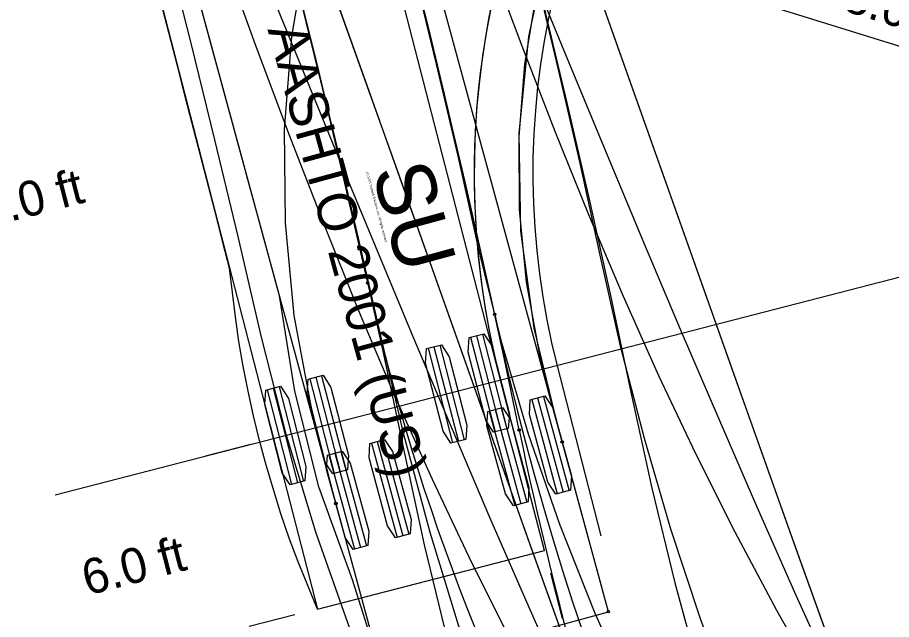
# Model space of a CAD drawing. Extents: x 916040 to 917457, y 328936 to 330267.
# Drawn here: x 916654.52 to 916684.33, y 329778.57 to 329799.1 of the extents above; entities that cross this region are included whole.
import ezdxf

# ---------------------------------------------------------------- set-up
doc = ezdxf.new("R2010")
doc.units = 0
for name, color, linetype in [('EB_LeftontoManchester_WB67', 7, 'Continuous'), ('EB_LeftontoManchester_WB67_v2', 7, 'Continuous'), ('NB_ThruontoManchester_WB67', 7, 'Continuous'), ('SU_IntoDriveway', 7, 'Continuous'), ('SU_IntoDriveway_Rt', 7, 'Continuous'), ('WB_RightontoManchester_WB67', 7, 'Continuous')]:
    doc.layers.add(name, color=color, linetype=linetype)

msp = doc.modelspace()

# ---------------------------------------------------------------- linework, layer by layer
at = {"layer": 'EB_LeftontoManchester_WB67'}
for points in [[(916682.241, 329777.749), (916681.118, 329780.876), (916680, 329784.008), (916678.884, 329787.143), (916677.771, 329790.282), (916676.657, 329793.423), (916675.541, 329796.565), (916674.423, 329799.708), (916673.299, 329802.851), (916672.17, 329805.993), (916671.034, 329809.133), (916669.889, 329812.272), (916668.734, 329815.408), (916667.569, 329818.541), (916666.392, 329821.67), (916665.202, 329824.794), (916663.999, 329827.914), (916662.781, 329831.029), (916661.548, 329834.138), (916660.298, 329837.24), (916659.033, 329840.337), (916657.749, 329843.426)], [(916678.932, 329775.573), (916677.819, 329778.595), (916676.808, 329781.65), (916675.901, 329784.736), (916675.099, 329787.849), (916674.397, 329790.994), (916673.698, 329794.181), (916672.962, 329797.377), (916672.193, 329800.579), (916671.392, 329803.785), (916670.559, 329806.993), (916669.696, 329810.202), (916668.803, 329813.41), (916667.88, 329816.616), (916666.928, 329819.819), (916665.947, 329823.018), (916664.938, 329826.212), (916663.901, 329829.401), (916662.836, 329832.582), (916661.742, 329835.757), (916660.621, 329838.924), (916659.472, 329842.082)], [(916669.601, 329778.228), (916668.593, 329781.538), (916667.695, 329784.881), (916666.908, 329788.244), (916666.151, 329791.57), (916665.373, 329794.873), (916664.574, 329798.156), (916663.752, 329801.421), (916662.906, 329804.669), (916662.034, 329807.902), (916661.138, 329811.12), (916660.215, 329814.324), (916659.267, 329817.515), (916658.293, 329820.694), (916657.292, 329823.861), (916656.265, 329827.016), (916655.212, 329830.159), (916654.132, 329833.291)], [(916673.116, 329778.01), (916671.993, 329781.154), (916670.875, 329784.298), (916669.76, 329787.441), (916668.646, 329790.581), (916667.532, 329793.719), (916666.416, 329796.854), (916665.297, 329799.984), (916664.174, 329803.111), (916663.044, 329806.232), (916661.907, 329809.349), (916660.762, 329812.46), (916659.607, 329815.564), (916658.441, 329818.663), (916657.264, 329821.754), (916656.074, 329824.839), (916654.871, 329827.916), (916653.654, 329830.986)]]:
    msp.add_lwpolyline(points, dxfattribs=at)
msp.add_circle((916670.794, 329788.972), 0.0417, dxfattribs=at)
msp.add_circle((916670.794, 329788.972), 0.0417, dxfattribs=at)
for centre, radius, start, end in [((916291.649, 329706.552), 388, 12.26429, 55.55708), ((916768.512, 329810.214), 100, 192.26429, 233.38938)]:
    msp.add_arc(centre, radius, start, end, dxfattribs=at)
at = {"layer": 'EB_LeftontoManchester_WB67_v2'}
for points in [[(916682.262, 329777.695), (916681.14, 329780.819), (916680.022, 329783.947), (916678.908, 329787.079), (916677.796, 329790.214), (916676.683, 329793.351), (916675.569, 329796.49), (916674.451, 329799.629), (916673.33, 329802.768), (916672.202, 329805.907), (916671.067, 329809.044), (916669.924, 329812.179), (916668.771, 329815.311), (916667.607, 329818.44), (916666.432, 329821.566), (916665.243, 329824.687), (916664.042, 329827.804), (916662.826, 329830.915), (916661.595, 329834.021), (916660.348, 329837.12), (916659.084, 329840.213), (916657.803, 329843.299)], [(916678.932, 329775.573), (916677.819, 329778.595), (916676.808, 329781.65), (916675.901, 329784.736), (916675.099, 329787.849), (916674.397, 329790.993), (916673.699, 329794.177), (916672.964, 329797.369), (916672.196, 329800.567), (916671.396, 329803.769), (916670.564, 329806.974), (916669.702, 329810.179), (916668.81, 329813.384), (916667.889, 329816.587), (916666.938, 329819.786), (916665.959, 329822.981), (916664.951, 329826.172), (916663.916, 329829.357), (916662.852, 329832.535), (916661.76, 329835.706), (916660.641, 329838.869), (916659.494, 329842.024)], [(916669.601, 329778.228), (916668.593, 329781.538), (916667.695, 329784.881), (916666.908, 329788.244), (916666.152, 329791.565), (916665.375, 329794.865), (916664.577, 329798.144), (916663.756, 329801.406), (916662.911, 329804.65), (916662.04, 329807.879), (916661.145, 329811.094), (916660.224, 329814.294), (916659.277, 329817.482), (916658.304, 329820.657), (916657.305, 329823.82), (916656.28, 329826.972), (916655.228, 329830.112), (916654.15, 329833.241)], [(916673.137, 329777.952), (916672.016, 329781.093), (916670.899, 329784.233), (916669.785, 329787.372), (916668.672, 329790.509), (916667.559, 329793.644), (916666.445, 329796.775), (916665.327, 329799.902), (916664.205, 329803.025), (916663.077, 329806.143), (916661.942, 329809.256), (916660.798, 329812.364), (916659.645, 329815.465), (916658.481, 329818.56), (916657.305, 329821.649), (916656.117, 329824.73), (916654.916, 329827.804), (916653.7, 329830.87)]]:
    msp.add_lwpolyline(points, dxfattribs=at)
msp.add_circle((916670.794, 329788.972), 0.0417, dxfattribs=at)
msp.add_circle((916670.794, 329788.972), 0.0417, dxfattribs=at)
for centre, radius, start, end in [((916291.649, 329706.552), 388, 12.26429, 55.55708), ((916768.512, 329810.214), 100, 192.26429, 233.38938)]:
    msp.add_arc(centre, radius, start, end, dxfattribs=at)
at = {"layer": 'NB_ThruontoManchester_WB67'}
for points in [[(916658.563, 329844.52), (916659.735, 329841.36), (916660.881, 329838.191), (916661.999, 329835.012), (916663.089, 329831.823), (916664.152, 329828.625), (916665.188, 329825.419), (916666.196, 329822.203), (916667.177, 329818.979), (916668.129, 329815.746), (916669.054, 329812.506), (916669.951, 329809.257), (916670.82, 329806.001), (916671.661, 329802.738), (916672.474, 329799.467), (916673.258, 329796.19), (916674.015, 329792.906), (916674.743, 329789.616), (916675.443, 329786.319), (916676.154, 329783.049), (916676.943, 329779.815), (916677.81, 329776.614)], [(916656.424, 329841.868), (916657.582, 329838.712), (916658.717, 329835.55), (916659.831, 329832.383), (916660.928, 329829.215), (916662.011, 329826.048), (916663.084, 329822.884), (916664.15, 329819.726), (916665.214, 329816.576), (916666.28, 329813.435), (916667.353, 329810.298), (916668.431, 329807.188), (916669.516, 329804.119), (916670.609, 329801.098), (916671.718, 329798.131), (916672.846, 329795.221), (916673.997, 329792.375), (916675.176, 329789.597), (916676.385, 329786.893), (916677.646, 329784.229), (916678.988, 329781.557), (916680.41, 329778.888), (916681.91, 329776.227)], [(916653.456, 329835.216), (916654.549, 329832.101), (916655.615, 329828.976), (916656.654, 329825.843), (916657.666, 329822.7), (916658.651, 329819.549), (916659.609, 329816.39), (916660.54, 329813.223), (916661.443, 329810.047), (916662.319, 329806.865), (916663.168, 329803.674), (916663.989, 329800.477), (916664.783, 329797.272), (916665.549, 329794.061), (916666.287, 329790.844), (916666.998, 329787.62), (916667.681, 329784.39), (916668.391, 329781.119), (916669.189, 329777.848)], [(916653.964, 329823.309), (916655.032, 329820.161), (916656.096, 329817.008), (916657.162, 329813.853), (916658.233, 329810.697), (916659.315, 329807.533), (916660.407, 329804.385), (916661.51, 329801.263), (916662.629, 329798.171), (916663.771, 329795.116), (916664.939, 329792.1), (916666.14, 329789.131), (916667.379, 329786.212), (916668.658, 329783.351), (916670, 329780.514), (916671.433, 329777.661)]]:
    msp.add_lwpolyline(points, dxfattribs=at)
msp.add_circle((916671.63, 329785.027), 0.0417, dxfattribs=at)
msp.add_circle((916671.63, 329785.027), 0.0417, dxfattribs=at)
for centre, radius, start, end in [((916291.649, 329706.552), 388, 11.6689, 55.55708), ((916800.902, 329811.725), 132, 191.6689, 207.94419)]:
    msp.add_arc(centre, radius, start, end, dxfattribs=at)
at = {"layer": 'SU_IntoDriveway'}
for p, q in [((916672.494, 329780.925), (916665.004, 329809.975)), ((916657.257, 329807.977), (916664.747, 329778.927)), ((916698.419, 329793.805), (916662.129, 329805.103)), ((916655.805, 329782.818), (916741.033, 329804.791)), ((916669.974, 329788.192), (916670.807, 329784.965)), ((916670.176, 329788.244), (916671.008, 329785.017)), ((916670.378, 329788.297), (916671.21, 329785.069)), ((916668.724, 329787.87), (916669.556, 329784.642)), ((916668.925, 329787.922), (916669.758, 329784.694)), ((916668.522, 329787.818), (916669.354, 329784.59)), ((916664.487, 329786.778), (916665.319, 329783.55)), ((916664.689, 329786.83), (916665.521, 329783.602)), ((916664.891, 329786.882), (916665.723, 329783.654)), ((916663.035, 329786.403), (916663.867, 329783.176)), ((916663.236, 329786.455), (916664.069, 329783.228)), ((916663.438, 329786.507), (916664.27, 329783.28)), ((916662.474, 329784.538), (916660.925, 329784.138)), ((916664.747, 329778.927), (916672.494, 329780.925)), ((916672.693, 329780.15), (916673.093, 329778.601)), ((916663.972, 329778.728), (916662.423, 329778.328))]:
    msp.add_line(p, q, dxfattribs=at)
for points in [[(916674.43, 329781.424), (916672.936, 329787.218), (916672.747, 329788.006), (916672.584, 329788.786), (916672.445, 329789.57), (916672.33, 329790.359), (916672.238, 329791.15), (916672.171, 329791.943), (916672.127, 329792.739), (916672.108, 329793.535), (916672.112, 329794.331), (916672.141, 329795.127), (916672.194, 329795.922), (916672.27, 329796.714), (916672.371, 329797.504), (916672.495, 329798.291), (916672.644, 329799.073), (916672.815, 329799.851)], [(916664.747, 329778.927), (916664.416, 329779.729), (916664.091, 329780.535), (916663.786, 329781.348), (916663.499, 329782.169), (916663.245, 329782.998), (916662.998, 329783.831), (916662.77, 329784.669), (916662.562, 329785.513), (916662.387, 329786.359), (916662.219, 329787.205), (916662.071, 329788.05), (916661.955, 329788.889), (916661.846, 329789.723), (916661.751, 329790.547), (916661.537, 329791.377), (916661.323, 329792.207), (916661.109, 329793.037), (916660.895, 329793.867), (916660.681, 329794.697), (916660.467, 329795.527), (916660.253, 329796.357), (916660.039, 329797.187), (916659.825, 329798.017), (916659.611, 329798.847), (916659.397, 329799.677)], [(916670.996, 329786.735), (916670.848, 329787.338), (916670.714, 329787.944), (916670.592, 329788.553), (916670.485, 329789.165), (916670.39, 329789.779), (916670.309, 329790.395), (916670.242, 329791.012), (916670.188, 329791.631), (916670.148, 329792.25), (916670.121, 329792.871), (916670.108, 329793.491), (916670.108, 329794.112), (916670.122, 329794.733), (916670.15, 329795.353), (916670.191, 329795.973), (916670.246, 329796.591), (916670.314, 329797.208), (916670.396, 329797.824), (916670.491, 329798.437), (916670.6, 329799.048), (916670.722, 329799.657)], [(916672.494, 329780.925), (916672.28, 329781.755), (916672.066, 329782.585), (916671.852, 329783.415), (916671.638, 329784.245), (916671.424, 329785.075), (916671.21, 329785.905), (916670.996, 329786.735), (916670.795, 329787.568), (916670.62, 329788.407), (916670.471, 329789.251), (916670.346, 329790.099), (916670.248, 329790.95), (916670.175, 329791.804), (916670.129, 329792.66), (916670.108, 329793.516), (916670.113, 329794.373), (916670.143, 329795.229), (916670.2, 329796.084), (916670.283, 329796.937), (916670.391, 329797.787), (916670.525, 329798.633), (916670.684, 329799.475)], [(916672.494, 329780.925), (916672.28, 329781.755), (916672.066, 329782.585), (916671.852, 329783.415), (916671.638, 329784.245), (916671.424, 329785.075), (916671.21, 329785.905), (916670.996, 329786.735), (916670.795, 329787.568), (916670.62, 329788.407), (916670.471, 329789.251), (916670.346, 329790.099), (916670.248, 329790.95), (916670.175, 329791.804), (916670.129, 329792.66), (916670.108, 329793.516), (916670.113, 329794.373), (916670.143, 329795.229), (916670.2, 329796.084), (916670.283, 329796.937), (916670.391, 329797.787), (916670.525, 329798.633), (916670.684, 329799.475)]]:
    msp.add_lwpolyline(points, dxfattribs=at)
for points in [[(916669.924, 329788.18), (916670.428, 329788.309), (916670.696, 329787.897), (916671.295, 329785.573), (916671.26, 329785.082), (916670.757, 329784.952), (916670.488, 329785.365), (916669.889, 329787.689)], [(916668.472, 329787.805), (916668.975, 329787.935), (916669.244, 329787.522), (916669.843, 329785.198), (916669.808, 329784.707), (916669.304, 329784.577), (916669.036, 329784.99), (916668.437, 329787.314)], [(916664.437, 329786.765), (916664.941, 329786.895), (916665.209, 329786.482), (916665.808, 329784.158), (916665.773, 329783.667), (916665.269, 329783.537), (916665.001, 329783.95), (916664.402, 329786.274)], [(916662.985, 329786.39), (916663.488, 329786.52), (916663.756, 329786.107), (916664.356, 329783.783), (916664.32, 329783.292), (916663.817, 329783.163), (916663.549, 329783.575), (916662.949, 329785.899)]]:
    msp.add_lwpolyline(points, close=True, dxfattribs=at)
at = {"layer": 'SU_IntoDriveway_Rt'}
for p, q in [((916674.672, 329778.835), (916666.793, 329807.782)), ((916659.074, 329805.681), (916666.953, 329776.734)), ((916672.257, 329786.124), (916673.132, 329782.907)), ((916672.458, 329786.178), (916673.333, 329782.962)), ((916671.01, 329785.784), (916671.886, 329782.568)), ((916672.056, 329786.069), (916672.931, 329782.852)), ((916670.608, 329785.675), (916671.484, 329782.459)), ((916670.809, 329785.73), (916671.685, 329782.513)), ((916666.588, 329784.581), (916667.463, 329781.364)), ((916666.789, 329784.635), (916667.664, 329781.419)), ((916666.99, 329784.69), (916667.865, 329781.474)), ((916665.543, 329784.296), (916666.418, 329781.08)), ((916665.141, 329784.187), (916666.016, 329780.97)), ((916665.342, 329784.241), (916666.217, 329781.025)), ((916666.953, 329776.734), (916674.672, 329778.835))]:
    msp.add_line(p, q, dxfattribs=at)
for points in [[(916665.377, 329782.524), (916664.541, 329785.79), (916663.959, 329788.933), (916663.656, 329792.099), (916663.629, 329795.28), (916663.88, 329798.451), (916664.406, 329801.588), (916665.203, 329804.667), (916666.265, 329807.666), (916667.584, 329810.56), (916669.151, 329813.328), (916670.952, 329815.95), (916672.975, 329818.404), (916675.205, 329820.673), (916677.623, 329822.739), (916680.212, 329824.587), (916682.952, 329826.202), (916685.823, 329827.572), (916688.802, 329828.687), (916689.409, 329828.879)], [(916673.096, 329784.625), (916672.333, 329787.599), (916671.878, 329790.074), (916671.643, 329792.546), (916671.625, 329795.029), (916671.824, 329797.505), (916672.237, 329799.953), (916672.862, 329802.357), (916673.694, 329804.697), (916674.726, 329806.955), (916675.951, 329809.115), (916677.36, 329811.16), (916678.942, 329813.075), (916680.684, 329814.844), (916682.574, 329816.455), (916684.597, 329817.895), (916686.738, 329819.154), (916688.98, 329820.221), (916691.307, 329821.089), (916691.78, 329821.239)], [(916674.672, 329778.835), (916673.797, 329782.052), (916672.922, 329785.268), (916672.14, 329788.508), (916671.691, 329791.807), (916671.63, 329795.135), (916671.957, 329798.445), (916672.667, 329801.693), (916673.75, 329804.834), (916675.191, 329807.827), (916675.191, 329807.827), (916675.191, 329807.827), (916675.516, 329808.395)], [(916666.953, 329776.734), (916665.944, 329779.917), (916664.801, 329783.092), (916663.977, 329786.352), (916663.451, 329789.6), (916662.576, 329792.816), (916661.7, 329796.032), (916660.825, 329799.249), (916659.95, 329802.465), (916659.074, 329805.681), (916659.074, 329805.681), (916658.946, 329806.345)]]:
    msp.add_lwpolyline(points, dxfattribs=at)
for points in [[(916672.006, 329786.055), (916672.508, 329786.192), (916672.781, 329785.783), (916673.412, 329783.467), (916673.383, 329782.975), (916672.881, 329782.839), (916672.607, 329783.248), (916671.977, 329785.564)], [(916670.558, 329785.661), (916671.06, 329785.798), (916671.334, 329785.389), (916671.964, 329783.073), (916671.936, 329782.582), (916671.434, 329782.445), (916671.16, 329782.854), (916670.53, 329785.17)], [(916666.538, 329784.567), (916667.04, 329784.704), (916667.313, 329784.294), (916667.944, 329781.979), (916667.915, 329781.487), (916667.413, 329781.351), (916667.14, 329781.76), (916666.509, 329784.076)], [(916665.091, 329784.173), (916665.592, 329784.31), (916665.866, 329783.901), (916666.496, 329781.585), (916666.468, 329781.093), (916665.966, 329780.957), (916665.692, 329781.366), (916665.062, 329783.682)]]:
    msp.add_lwpolyline(points, close=True, dxfattribs=at)
for centre in [(916673.096, 329784.625), (916665.377, 329782.524), (916674.672, 329778.835)]:
    msp.add_circle(centre, 0.0417, dxfattribs=at)
at = {"layer": 'WB_RightontoManchester_WB67'}
for points in [[(916682.431, 329776.405), (916681.081, 329779.393), (916679.751, 329782.399), (916678.437, 329785.421), (916677.138, 329788.456), (916675.851, 329791.503), (916674.574, 329794.56), (916673.306, 329797.625), (916672.043, 329800.697), (916670.785, 329803.775), (916669.529, 329806.857), (916668.273, 329809.942), (916667.016, 329813.029), (916665.756, 329816.117), (916664.492, 329819.205), (916663.221, 329822.292), (916661.943, 329825.378), (916660.657, 329828.461), (916659.361, 329831.542), (916658.054, 329834.618), (916656.736, 329837.69), (916655.404, 329840.757), (916654.059, 329843.818)], [(916675.571, 329775.79), (916674.221, 329778.778), (916673.014, 329781.811), (916671.952, 329784.886), (916671.034, 329787.997), (916670.261, 329791.139), (916669.556, 329794.318), (916668.814, 329797.507), (916668.038, 329800.703), (916667.229, 329803.904), (916666.388, 329807.107), (916665.516, 329810.311), (916664.613, 329813.515), (916663.681, 329816.716), (916662.719, 329819.915), (916661.727, 329823.11), (916660.707, 329826.3), (916659.659, 329829.484), (916658.582, 329832.661), (916657.477, 329835.831), (916656.343, 329838.994), (916655.182, 329842.148)], [(916673.323, 329775.921), (916671.967, 329778.983), (916670.633, 329782.053), (916669.316, 329785.129), (916668.014, 329788.211), (916666.726, 329791.297), (916665.448, 329794.384), (916664.178, 329797.474), (916662.915, 329800.563), (916661.657, 329803.651), (916660.4, 329806.738), (916659.144, 329809.822), (916657.887, 329812.902), (916656.628, 329815.979), (916655.364, 329819.051), (916654.094, 329822.118)], [(916665.856, 329778.266), (916664.698, 329781.552), (916663.682, 329784.894), (916662.813, 329788.286), (916662.041, 329791.623), (916661.252, 329794.929), (916660.442, 329798.214), (916659.609, 329801.48), (916658.752, 329804.729), (916657.87, 329807.961), (916656.962, 329811.178), (916656.029, 329814.381), (916655.07, 329817.571), (916654.084, 329820.747)]]:
    msp.add_lwpolyline(points, dxfattribs=at)
msp.add_circle((916666.462, 329790.046), 0.0417, dxfattribs=at)
msp.add_circle((916666.462, 329790.046), 0.0417, dxfattribs=at)
for centre, radius, start, end in [((916291.649, 329706.552), 384, 12.55823, 55.55708), ((916739.667, 329806.353), 75, 192.55823, 210.31996)]:
    msp.add_arc(centre, radius, start, end, dxfattribs=at)

# ---------------------------------------------------------------- texts
at = {"layer": 'SU_IntoDriveway'}
for s, rotation, p in [('38.0 ft', 342.7069, (916681.763, 329799.618)), ('20.0 ft', 14.4569, (916652.547, 329791.686)), ('6.0 ft', 14.4569, (916656.899, 329779.383))]:
    msp.add_text(s, height=1.2, rotation=rotation, dxfattribs=at).set_placement(p)
at = {"layer": 'SU_IntoDriveway_Rt'}
for s, height, p in [('AASHTO 2001 (US)', 1.33333, (916663.042, 329798.692)), ('SU', 2, (916666.602, 329793.863)), ('(c) 2016 Transoft Solutions, Inc. All rights reserved.', 0.08, (916666.406, 329793.821))]:
    msp.add_text(s, height=height, rotation=285.2259, dxfattribs=at).set_placement(p)

doc.saveas('drawing.dxf')
